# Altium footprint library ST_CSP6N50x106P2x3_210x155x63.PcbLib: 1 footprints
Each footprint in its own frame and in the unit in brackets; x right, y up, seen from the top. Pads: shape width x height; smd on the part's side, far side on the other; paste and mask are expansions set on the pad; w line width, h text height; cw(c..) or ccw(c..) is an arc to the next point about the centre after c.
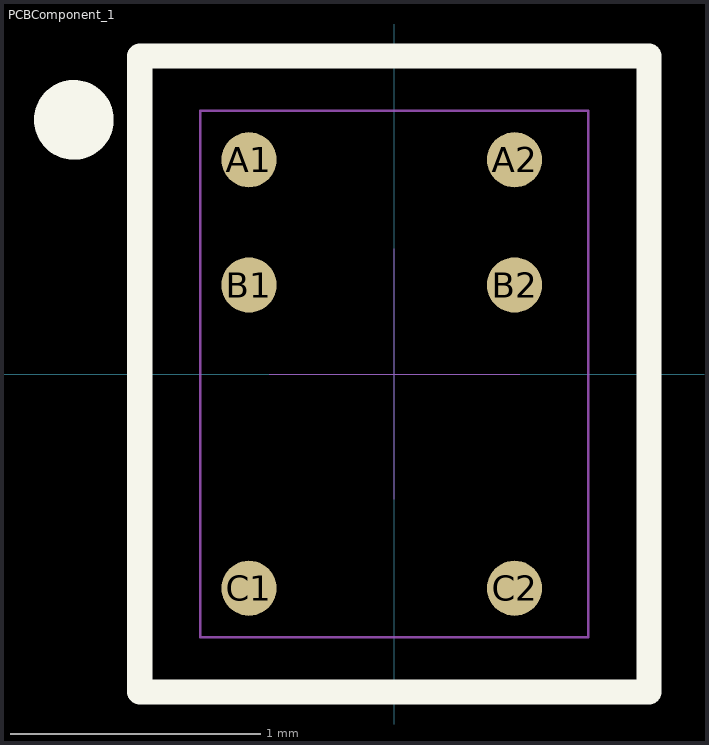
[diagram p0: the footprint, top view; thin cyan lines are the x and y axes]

## PCBComponent_1 [mm]
pads (6):
  round 0.22 smd paste-20 mask+0.05: A1(-0.58,0.855) A2(0.48,0.855) B1(-0.58,0.355) B2(0.48,0.355) C1(-0.58,-0.855) C2(0.48,-0.855)
Top Overlay:
  circle w0.2: c-1.279,1.014 r0.059
  lines w0.1: -1.016,-1.27 1.016,-1.27 1.016,1.27 -1.016,1.27 -1.016,-1.27
Top Paste:
  rectangle: 0.37,-0.965 0.59,-0.745
  rectangle: -0.69,-0.965 -0.47,-0.745
  rectangle: -0.69,0.245 -0.47,0.465
  rectangle: 0.37,0.245 0.59,0.465
  rectangle: 0.37,0.745 0.59,0.965
  rectangle: -0.69,0.745 -0.47,0.965
Mechanical 15:
  lines w0.001: -0.5,0 0.5,0 ; 0,-0.5 0,0.5
  lines w0.01: -0.775,-1.05 0.775,-1.05 0.775,1.05 -0.775,1.05 -0.775,-1.05
3D body: height 0.68, standoff 0.18, extent -0.775,-1.05 0.775,1.05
